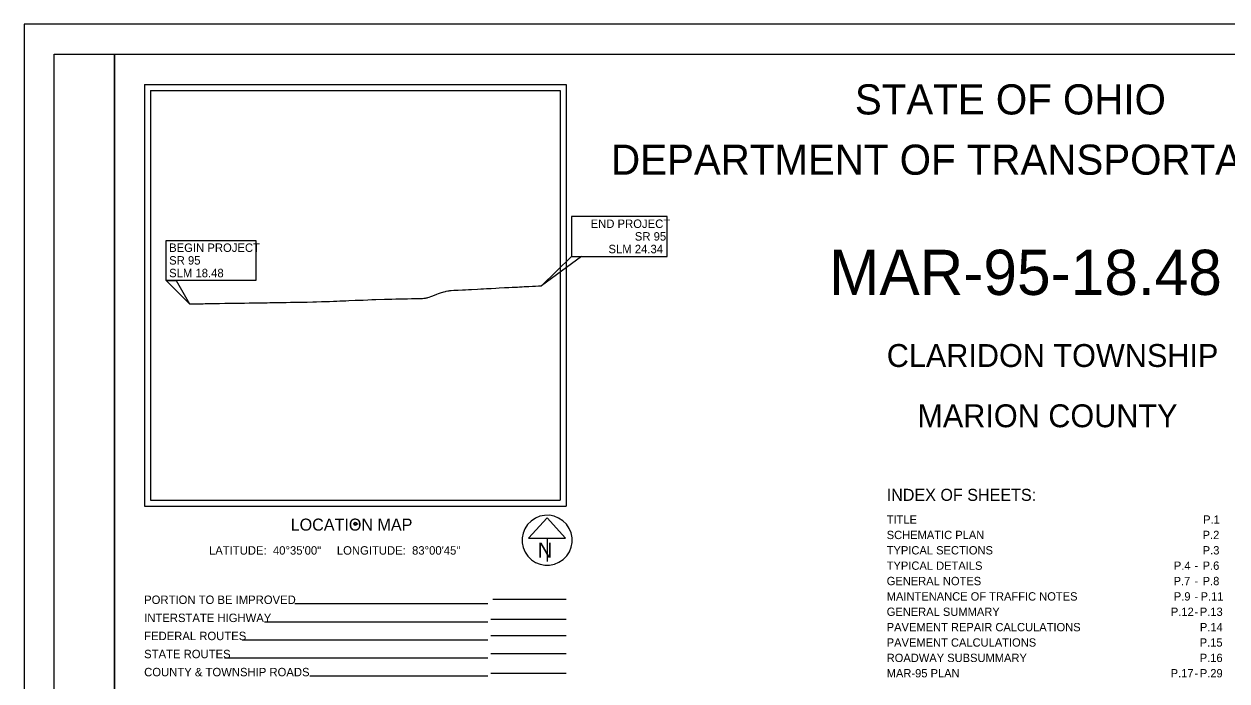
# Model space of a CAD drawing. Extents: x 0 to 34, y 0 to 22.
# Drawn here: x 0 to 19.97, y 11.1 to 22 of the extents above; entities that cross this region are included whole.
import ezdxf

# ---------------------------------------------------------------- set-up
doc = ezdxf.new("R2010")
doc.units = 0
for name, color, linetype in [('GM_X_County', 7, 'Continuous'), ('GM_X_Minor_Lake', 7, 'Continuous'), ('GM_X_Minor_Lake_Text', 7, 'Continuous'), ('GM_X_Minor_River_Text', 7, 'Continuous')]:
    doc.layers.add(name, color=color, linetype=linetype)

msp = doc.modelspace()

# ---------------------------------------------------------------- linework, layer by layer
at = {"layer": 'GM_X_County'}
msp.add_lwpolyline([(0, 0), (34, 0), (34, 22), (0, 22)], close=True, dxfattribs=at)
at = {"layer": 'GM_X_Minor_Lake'}
for p, q in [((5.474, 13.708), (5.526, 13.708)), ((5.5, 13.708), (5.549, 13.708))]:
    msp.add_line(p, q, dxfattribs=at)
for points in [[(10.68, 18.807), (9.091, 18.807), (9.091, 18.141), (10.68, 18.141)], [(2.359, 18.409), (3.848, 18.409), (3.848, 17.743), (2.359, 17.743)], [(8.592, 17.658), (9.091, 18.141), (9.254, 18.141)], [(2.749, 17.355), (2.359, 17.743), (2.523, 17.743)]]:
    msp.add_lwpolyline(points, close=True, dxfattribs=at)
msp.add_circle((5.5, 13.708), 0.026, dxfattribs=at)
at = {"layer": 'GM_X_Minor_Lake_Text'}
for p, q in [((2, 21), (9, 21)), ((2, 21), (2, 14)), ((9, 21), (9, 14)), ((2.1, 20.9), (2.1, 14.1)), ((2.1, 20.9), (8.9, 20.9)), ((8.9, 20.9), (8.9, 14.1)), ((2.749, 17.355), (2.768, 17.356)), ((2, 14), (9, 14)), ((2.1, 14.1), (8.9, 14.1)), ((2.1, 14.1), (2.1, 14.1)), ((8.685, 13.809), (8.377, 13.468)), ((8.992, 13.468), (8.685, 13.809)), ((8.377, 13.468), (8.992, 13.468)), ((8.685, 13.468), (8.685, 13.081)), ((8.685, 13.435), (8.685, 13.435)), ((8.685, 13.435), (8.685, 13.435)), ((7.783, 12.455), (9, 12.455)), ((7.7, 12.377), (4.494, 12.377)), ((7.7, 12.077), (3.99, 12.077)), ((9, 12.121), (7.75, 12.121)), ((9, 11.849), (7.75, 11.849)), ((7.7, 11.777), (3.619, 11.777)), ((7.7, 11.477), (3.329, 11.477)), ((9, 11.549), (7.75, 11.549)), ((9, 11.222), (7.75, 11.222)), ((7.7, 11.177), (4.745, 11.177))]:
    msp.add_line(p, q, dxfattribs=at)
for points in [[(6.972, 17.558), (6.975, 17.559), (6.996, 17.564), (7.011, 17.568), (7.035, 17.572), (7.057, 17.576), (7.072, 17.578), (7.094, 17.58), (7.137, 17.583), (7.159, 17.584)], [(7.137, 17.583), (7.147, 17.583), (7.21, 17.586), (7.279, 17.59), (7.327, 17.592), (7.38, 17.595), (7.428, 17.597), (7.526, 17.603), (7.583, 17.605), (7.591, 17.606), (7.605, 17.607), (7.63, 17.608), (7.677, 17.61), (7.753, 17.614), (7.832, 17.618), (7.889, 17.621), (7.977, 17.626), (8.05, 17.629), (8.104, 17.632), (8.164, 17.635), (8.195, 17.637), (8.224, 17.639), (8.268, 17.641), (8.306, 17.643), (8.344, 17.645), (8.354, 17.645), (8.382, 17.647), (8.442, 17.65), (8.489, 17.653), (8.543, 17.655), (8.589, 17.658)], [(3.007, 17.361), (3.019, 17.361), (3.091, 17.362), (3.14, 17.363), (3.181, 17.364), (3.246, 17.365), (3.333, 17.366), (3.398, 17.367), (3.454, 17.368), (3.526, 17.369), (3.557, 17.37), (3.622, 17.371), (3.66, 17.371), (3.737, 17.373), (3.8, 17.373), (3.865, 17.375), (3.911, 17.376), (3.961, 17.376), (3.995, 17.377), (4.036, 17.377), (4.082, 17.378), (4.179, 17.38), (4.253, 17.38), (4.296, 17.381), (4.352, 17.382), (4.423, 17.383), (4.454, 17.384), (4.498, 17.384), (4.557, 17.385), (4.581, 17.386), (4.631, 17.387), (4.699, 17.388), (4.792, 17.391), (4.858, 17.393), (4.941, 17.396), (5.022, 17.398), (5.069, 17.399), (5.14, 17.402), (5.193, 17.404), (5.245, 17.405), (5.295, 17.407), (5.338, 17.409), (5.342, 17.41), (5.394, 17.411), (5.497, 17.416), (5.559, 17.418), (5.628, 17.421), (5.706, 17.424), (5.775, 17.427), (5.833, 17.429), (5.838, 17.429), (5.987, 17.434), (6.034, 17.435), (6.105, 17.437), (6.174, 17.439), (6.254, 17.441), (6.307, 17.443), (6.36, 17.443), (6.364, 17.443)], [(6.364, 17.443), (6.431, 17.444), (6.466, 17.445), (6.481, 17.445), (6.512, 17.445), (6.541, 17.446)], [(6.541, 17.446), (6.549, 17.446), (6.59, 17.447), (6.614, 17.448), (6.636, 17.449), (6.648, 17.45), (6.664, 17.453), (6.679, 17.456), (6.691, 17.459), (6.706, 17.463), (6.726, 17.47), (6.753, 17.479), (6.787, 17.492), (6.851, 17.517), (6.883, 17.529), (6.933, 17.546), (6.954, 17.553), (6.972, 17.558)], [(2.768, 17.356), (2.799, 17.357), (2.811, 17.357)], [(2.811, 17.357), (2.815, 17.358), (2.889, 17.359), (2.932, 17.36), (2.973, 17.36), (3.007, 17.361)]]:
    msp.add_lwpolyline(points, dxfattribs=at)
msp.add_arc((8.685, 13.435), 0.415, 129.7798, 129.7633, dxfattribs=at)
at = {"layer": 'GM_X_Minor_River_Text'}
for points in [[(0.5, 21.5), (1.5, 21.5), (1.5, 0.5), (0.5, 0.5)], [(1.5, 21.5), (33.5, 21.5), (33.5, 0.5), (1.5, 0.5)]]:
    msp.add_lwpolyline(points, close=True, dxfattribs=at)

# ---------------------------------------------------------------- texts
at = {"layer": 'GM_X_Minor_Lake'}
for s, height, p in [('STATE OF OHIO', 0.5, (13.795, 20.5)), ('DEPARTMENT OF TRANSPORTATION', 0.5, (9.747, 19.5)), ('END PROJECT', 0.14, (9.407, 18.617)), ('SR 95', 0.14, (10.141, 18.407)), ('BEGIN PROJECT', 0.14, (2.409, 18.219)), ('SLM 24.34', 0.14, (9.704, 18.197)), ('MAR-95-18.48', 0.75, (13.366, 17.505)), ('SR 95', 0.14, (2.409, 18.009)), ('SLM 18.48', 0.14, (2.409, 17.799)), ('CLARIDON TOWNSHIP', 0.38, (14.324, 16.31)), ('MARION COUNTY', 0.38, (14.832, 15.31)), ('INDEX OF SHEETS:', 0.2, (14.323, 14.088)), ('LOCATION MAP', 0.2, (4.427, 13.594)), ('TITLE', 0.138, (14.323, 13.709)), ('P.1', 0.138, (19.577, 13.709)), ('P.1', 0.00328, (5.497, 13.698)), ('1', 0.00328, (5.499, 13.714)), ('Drawing', 0.00328, (5.532, 13.714)), ('1:1', 0.00328, (5.532, 13.698)), ('SCHEMATIC PLAN', 0.138, (14.323, 13.454)), ('P.2', 0.138, (19.569, 13.454)), ('LATITUDE:  40°35\'00"     LONGITUDE:  83°00\'45"', 0.14, (3.071, 13.196)), ('TYPICAL SECTIONS', 0.138, (14.323, 13.199)), ('P.3', 0.138, (19.57, 13.199)), ('TYPICAL DETAILS', 0.138, (14.323, 12.944)), ('P.4', 0.138, (19.091, 12.944)), ('-', 0.138, (19.431, 12.944)), ('P.6', 0.138, (19.569, 12.944)), ('GENERAL NOTES', 0.138, (14.323, 12.689)), ('P.7', 0.138, (19.087, 12.689)), ('P.8', 0.138, (19.569, 12.689)), ('-', 0.138, (19.431, 12.689)), ('PORTION TO BE IMPROVED', 0.14, (1.994, 12.377)), ('MAINTENANCE OF TRAFFIC NOTES', 0.138, (14.323, 12.434)), ('P.9', 0.138, (19.09, 12.434)), ('-', 0.138, (19.431, 12.434)), ('P.11', 0.138, (19.535, 12.434)), ('INTERSTATE HIGHWAY', 0.14, (1.994, 12.077)), ('GENERAL SUMMARY', 0.138, (14.323, 12.179)), ('P.12', 0.138, (19.041, 12.179)), ('-', 0.138, (19.431, 12.179)), ('P.13', 0.138, (19.522, 12.179)), ('PAVEMENT REPAIR CALCULATIONS', 0.138, (14.323, 11.924)), ('P.14', 0.138, (19.523, 11.924)), ('FEDERAL ROUTES', 0.14, (1.994, 11.777)), ('PAVEMENT CALCULATIONS', 0.138, (14.323, 11.669)), ('P.15', 0.138, (19.52, 11.669)), ('STATE ROUTES', 0.14, (1.994, 11.477)), ('ROADWAY SUBSUMMARY', 0.138, (14.323, 11.414)), ('P.16', 0.138, (19.521, 11.414)), ('COUNTY & TOWNSHIP ROADS', 0.14, (1.994, 11.177)), ('MAR-95 PLAN', 0.138, (14.323, 11.159)), ('P.17', 0.138, (19.038, 11.159)), ('-', 0.138, (19.431, 11.159)), ('P.29', 0.138, (19.522, 11.159))]:
    msp.add_text(s, height=height, dxfattribs=at).set_placement(p)
at = {"layer": 'GM_X_Minor_Lake_Text'}
msp.add_text('N', height=0.25, dxfattribs=at).set_placement((8.529, 13.144))

doc.saveas('drawing.dxf')
